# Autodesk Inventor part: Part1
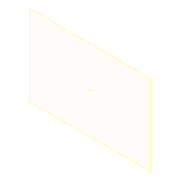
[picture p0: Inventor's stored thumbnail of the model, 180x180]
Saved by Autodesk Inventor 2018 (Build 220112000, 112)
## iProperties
Created: 2015-07
Part Number: Part1
Material: Generic
Document SubType Name: Modeling
Designer: Sandeep
Density: 1 g/cm^3
Appearance: Default
Author: Sandeep
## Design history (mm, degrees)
sketch "Sketch1"
  geometry: 1 further point
  constraints: 1 other
feature "Form1"
body "Srf1"
